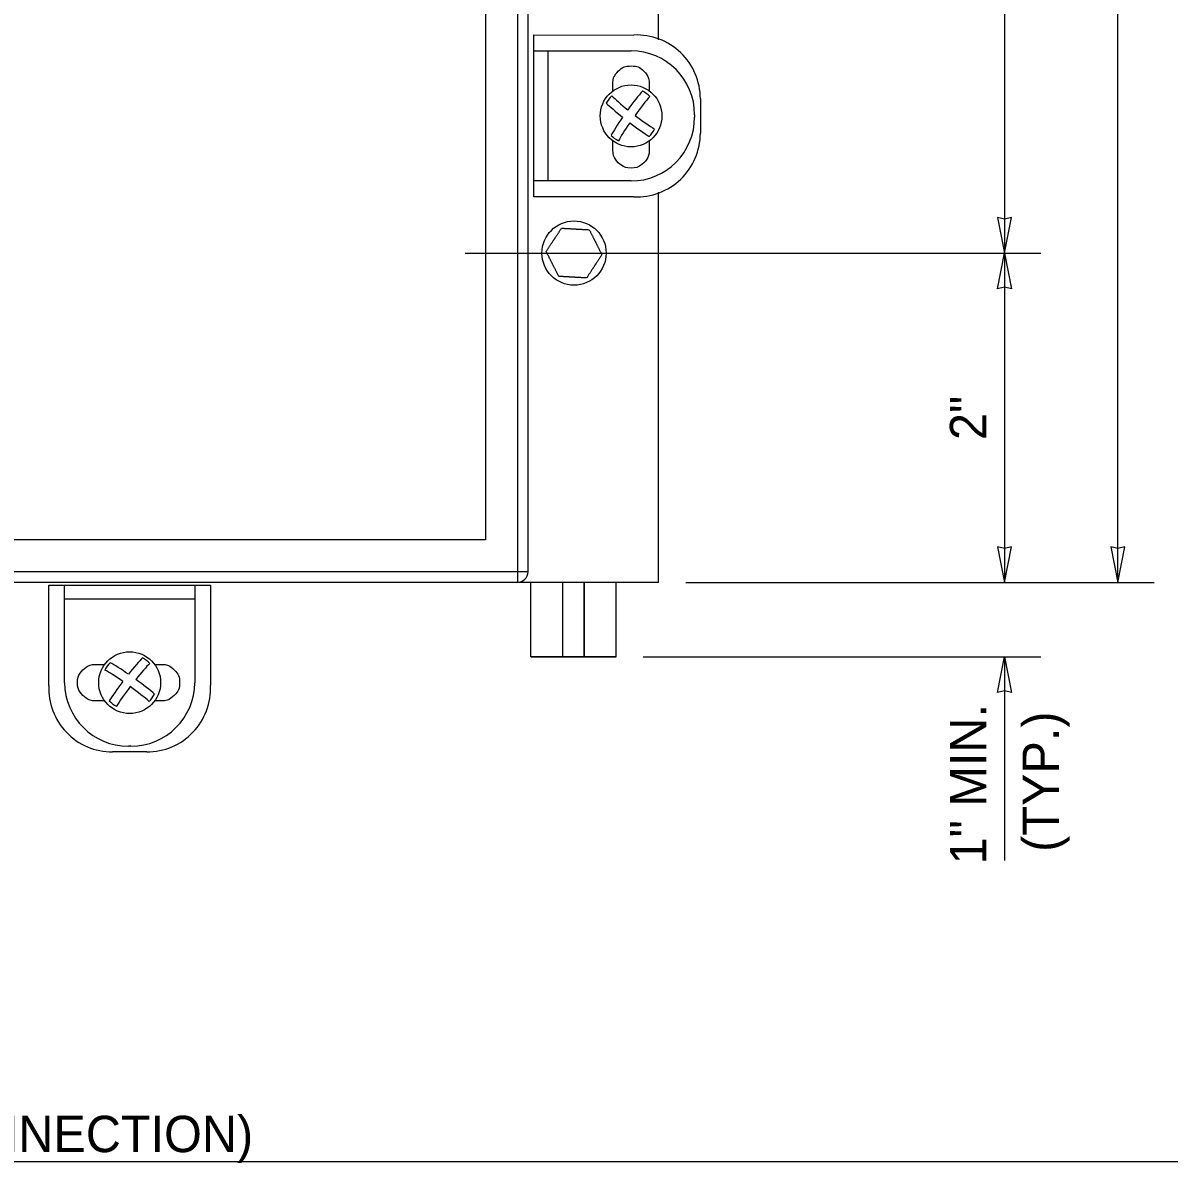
# Model space of a CAD drawing. Extents: x 99862 to 104211, y 98939 to 102076.
# Drawn here: x 101435 to 101940, y 99999 to 100501 of the extents above; entities that cross this region are included whole.
import ezdxf

# ---------------------------------------------------------------- set-up
doc = ezdxf.new("R2010")
doc.units = 0
for name, color, linetype in [('Level 1', 7, 'Continuous'), ('Level 11', 7, 'Continuous'), ('Level 15', 7, 'Continuous'), ('Level 17', 7, 'Continuous'), ('Level 18', 7, 'Continuous'), ('Level 19', 7, 'Continuous'), ('Level 20', 7, 'Continuous'), ('Level 6', 7, 'Continuous'), ('Level 9', 7, 'Continuous')]:
    doc.layers.add(name, color=color, linetype=linetype)

msp = doc.modelspace()

# ---------------------------------------------------------------- linework, layer by layer
at = {"layer": 'Level 1'}
for p, q in [((101652.84, 101082.12), (101652.84, 100254.51)), ((101657.52, 101077.44), (101657.52, 100259.2)), ((101638.77, 101063.37), (101638.77, 100273.26)), ((101638.77, 100273.26), (101021.35, 100273.26)), ((101657.52, 100259.2), (100982.51, 100259.2)), ((101652.84, 100254.51), (100987.19, 100254.51))]:
    msp.add_line(p, q, dxfattribs=at)
msp.add_lwpolyline([(99862, 99999.5), (103151, 99999.5), (103151, 102075.5), (99862, 102075.5)], close=True, dxfattribs=at)
msp.add_arc((101652.84, 100259.2), 4.69, 270, 360, dxfattribs=at)
at = {"layer": 'Level 11'}
for centre, major_axis in [((101702.93, 100459.93), (0, 13.65)), ((101482.08, 100210.36), (13.65, 0))]:
    msp.add_ellipse(centre, major_axis=major_axis, ratio=0.995235, dxfattribs=at)
for centre, major_axis, ratio, start_param, end_param in [((101702.64, 100459.84), (-3.51, 11.61), 0.995235, 0.450926, 0.782886), ((101704.61, 100461.66), (-11.37, 8.76), 0.079461, 0.529016, 1.356129), ((101701.79, 100461.08), (8.35, 11.69), 0.079461, 0.642258, 1.493468), ((101705.04, 100458.76), (-8.35, -11.68), 0.079461, 3.784049, 4.646796), ((101702.63, 100459.93), (0, -12.13), 0.995235, 2.356141, 2.688101), ((101702.17, 100458.5), (11.38, -8.77), 0.079461, 3.67041, 4.509515), ((101701.79, 100461.08), (8.35, 11.69), 0.079461, 1.773671, 2.612775), ((101705.04, 100458.76), (-8.35, -11.68), 0.079461, 4.927057, 5.75417), ((101702.17, 100458.5), (11.38, -8.77), 0.079461, 4.789717, 5.640927), ((101704.61, 100461.66), (-11.37, 8.76), 0.079461, 1.636389, 2.499136), ((101702.64, 100459.84), (-3.51, 11.61), 0.995235, 3.595085, 3.927044), ((101702.63, 100459.93), (0, -12.13), 0.995235, 5.5003, 5.83226), ((101480.65, 100211.11), (-8.77, -11.38), 0.079461, 3.67041, 4.509515), ((101482, 100210.64), (11.61, 3.51), 0.995235, 0.450926, 0.782886), ((101482.08, 100210.65), (-12.13, 0), 0.995235, 5.5003, 5.83226), ((101480.91, 100208.24), (-11.68, 8.35), 0.079461, 4.927057, 5.75417), ((101483.24, 100211.49), (11.69, -8.35), 0.079461, 1.773671, 2.612775), ((101483.82, 100208.67), (8.76, 11.37), 0.079461, 0.529016, 1.356129), ((101480.65, 100211.11), (-8.77, -11.38), 0.079461, 4.789717, 5.640927), ((101483.24, 100211.49), (11.69, -8.35), 0.079461, 0.642258, 1.493468), ((101483.82, 100208.67), (8.76, 11.37), 0.079461, 1.636389, 2.499136), ((101480.91, 100208.24), (-11.68, 8.35), 0.079461, 3.784049, 4.646796), ((101482.08, 100210.65), (-12.13, 0), 0.995235, 2.356141, 2.688101), ((101482, 100210.64), (11.61, 3.51), 0.995235, 3.595085, 3.927044)]:
    msp.add_ellipse(centre, major_axis=major_axis, ratio=ratio, start_param=start_param, end_param=end_param, dxfattribs=at)
at = {"layer": 'Level 15'}
for p, q in [((101917.34, 100254.51), (101917.34, 101082.12)), ((101867.34, 100668.32), (101867.34, 100399.54)), ((101629.8, 100399.54), (101883.34, 100399.54)), ((101867.34, 100399.54), (101867.34, 100254.51)), ((101727.06, 100254.51), (101933.34, 100254.51)), ((101708.31, 100221.7), (101883.34, 100221.7)), ((101867.34, 100221.7), (101867.34, 100132.03))]:
    msp.add_line(p, q, dxfattribs=at)
for points in [[(101867.34, 100399.54), (101870.43, 100415.26), (101867.34, 100414.53), (101864.26, 100415.26)], [(101867.34, 100399.54), (101870.43, 100383.81), (101867.34, 100384.54), (101864.26, 100383.81)], [(101867.34, 100254.51), (101870.43, 100270.24), (101867.34, 100269.51), (101864.26, 100270.24)], [(101917.34, 100254.51), (101920.43, 100270.24), (101917.34, 100269.51), (101914.26, 100270.24)], [(101867.34, 100221.7), (101870.43, 100205.98), (101867.34, 100206.7), (101864.26, 100205.98)]]:
    msp.add_lwpolyline(points, close=True, dxfattribs=at)
at = {"layer": 'Level 17'}
for p, q in [((101658.81, 100221.7), (101658.81, 100254.51)), ((101682.25, 100254.51), (101682.25, 100221.7)), ((101682.25, 100221.7), (101682.25, 100254.51)), ((101658.81, 100221.7), (101658.81, 100221.7)), ((101663.5, 100221.7), (101663.5, 100221.7))]:
    msp.add_line(p, q, dxfattribs=at)
for points in [[(101658.81, 100221.7), (101672.87, 100221.7), (101672.87, 100254.51)], [(101696.31, 100221.7), (101658.81, 100221.7), (101658.81, 100254.51)], [(101672.87, 100221.7), (101672.87, 100254.51)], [(101682.25, 100221.7), (101696.31, 100221.7), (101696.31, 100254.51)], [(101696.31, 100221.7), (101696.31, 100254.51)], [(101663.5, 100221.7), (101691.62, 100221.7), (101691.62, 100221.7)], [(101668.19, 100221.7), (101663.5, 100221.7), (101663.5, 100221.7)], [(101672.87, 100221.7), (101668.19, 100221.7), (101668.19, 100221.7)], [(101668.19, 100221.7), (101668.19, 100221.7), (101668.19, 100221.7)], [(101682.25, 100221.7), (101682.25, 100221.7), (101686.94, 100221.7), (101686.94, 100221.7)], [(101691.62, 100221.7), (101686.94, 100221.7), (101686.94, 100221.7)], [(101691.62, 100221.7), (101691.62, 100221.7), (101691.62, 100221.7)]]:
    msp.add_lwpolyline(points, dxfattribs=at)
at = {"layer": 'Level 18'}
for p, q in [((101696.24, 100254.51), (101652.84, 100254.51)), ((101715.06, 100254.51), (101696.26, 100254.51))]:
    msp.add_line(p, q, dxfattribs=at)
for points in [[(101715.06, 100493.46), (101715.06, 100555.19)], [(101715.06, 100254.51), (101715.06, 100426.4)]]:
    msp.add_lwpolyline(points, dxfattribs=at)
at = {"layer": 'Level 19'}
msp.add_circle((101677.8, 100399.54), 14.14, dxfattribs=at)
for points in [[(101665.53, 100400.23), (101667.76, 100403.63), (101670.03, 100407.1), (101672.26, 100410.5)], [(101672.26, 100410.5), (101676.35, 100410.27), (101680.44, 100410.04), (101684.53, 100409.81)], [(101684.53, 100409.81), (101686.37, 100406.15), (101688.22, 100402.5), (101690.06, 100398.84)], [(101671.06, 100389.26), (101669.22, 100392.92), (101667.38, 100396.57), (101665.53, 100400.23)], [(101690.06, 100398.84), (101687.83, 100395.44), (101685.56, 100391.97), (101683.33, 100388.57)], [(101683.33, 100388.57), (101679.24, 100388.8), (101675.15, 100389.03), (101671.06, 100389.26)]]:
    msp.add_open_spline(points, degree=2, dxfattribs=at)
at = {"layer": 'Level 6'}
for p, q in [((101660.06, 100495.57), (101704.19, 100495.54)), ((101733.44, 100467.45), (101733.44, 100452.41)), ((101704.19, 100424.32), (101660.06, 100424.29)), ((101446.47, 100209.09), (101446.44, 100253.23)), ((101517.72, 100253.23), (101517.7, 100209.09)), ((101489.6, 100179.84), (101474.57, 100179.84))]:
    msp.add_line(p, q, dxfattribs=at)
for centre, major_axis, start_param, end_param in [((101705.45, 100467.45), (0, 28.12), 4.712389, 6.328322), ((101705.45, 100452.41), (0, 28.12), 3.096456, 4.712389), ((101474.57, 100207.83), (28.12, 0), 3.096456, 4.712389), ((101489.6, 100207.83), (28.12, 0), 4.712389, 6.328322)]:
    msp.add_ellipse(centre, major_axis=major_axis, ratio=0.995235, start_param=start_param, end_param=end_param, dxfattribs=at)
at = {"layer": 'Level 9'}
for p, q in [((101660.06, 100424.29), (101660.06, 100495.57)), ((101660.06, 100488.57), (101672.33, 100488.57)), ((101666.19, 100488.57), (101666.19, 100431.29)), ((101672.33, 100488.57), (101674.95, 100488.57)), ((101674.95, 100488.57), (101679.64, 100488.57)), ((101679.65, 100488.57), (101702.93, 100488.57)), ((101694.91, 100470.95), (101694.91, 100473.89)), ((101710.94, 100473.89), (101710.94, 100470.95)), ((101730.92, 100460.45), (101730.92, 100459.41)), ((101694.91, 100445.02), (101694.91, 100448.91)), ((101710.94, 100448.91), (101710.94, 100445.02)), ((101672.33, 100431.29), (101660.06, 100431.29)), ((101674.95, 100431.29), (101672.33, 100431.29)), ((101679.64, 100431.29), (101674.95, 100431.29)), ((101702.93, 100431.29), (101679.65, 100431.29)), ((101446.44, 100253.23), (101517.72, 100253.23)), ((101453.44, 100240.96), (101453.44, 100253.23)), ((101510.72, 100253.23), (101510.72, 100240.96)), ((101510.72, 100247.09), (101453.44, 100247.09)), ((101453.44, 100238.33), (101453.44, 100240.96)), ((101510.72, 100240.96), (101510.72, 100238.33)), ((101453.44, 100233.64), (101453.44, 100238.33)), ((101510.72, 100238.33), (101510.72, 100233.64)), ((101453.44, 100210.36), (101453.44, 100233.64)), ((101510.72, 100233.64), (101510.72, 100210.36)), ((101467.17, 100218.37), (101471.06, 100218.37)), ((101493.11, 100218.37), (101496.05, 100218.37)), ((101471.06, 100202.35), (101467.17, 100202.35)), ((101496.05, 100202.35), (101493.11, 100202.35)), ((101482.6, 100182.37), (101481.57, 100182.37))]:
    msp.add_line(p, q, dxfattribs=at)
for centre, major_axis, start_param, end_param in [((101702.93, 100460.45), (0, 28.12), 4.712389, 6.283185), ((101702.93, 100459.41), (0, 28.12), 3.141593, 4.712389), ((101481.57, 100210.36), (28.12, 0), 3.141593, 4.712389), ((101482.6, 100210.36), (28.12, 0), 4.712389, 6.283185)]:
    msp.add_ellipse(centre, major_axis=major_axis, ratio=0.995235, start_param=start_param, end_param=end_param, dxfattribs=at)
for points in [[(101694.91, 100473.89), (101694.91, 100473.89), (101694.91, 100473.89), (101694.91, 100476.04), (101695.76, 100478.1), (101698.78, 100481.13), (101700.81, 100481.97), (101705.05, 100481.97), (101707.08, 100481.13), (101710.09, 100478.1), (101710.94, 100476.04), (101710.94, 100473.89)], [(101702.93, 100436.94), (101700.81, 100436.94), (101698.78, 100437.78), (101695.76, 100440.81), (101694.91, 100442.87), (101694.91, 100445.02)], [(101710.94, 100445.02), (101710.94, 100442.87), (101710.09, 100440.81), (101707.08, 100437.78), (101705.05, 100436.94), (101702.93, 100436.94)], [(101459.1, 100210.36), (101459.1, 100212.48), (101459.94, 100214.51), (101462.97, 100217.52), (101465.02, 100218.37), (101467.17, 100218.37)], [(101496.05, 100218.37), (101496.05, 100218.37), (101496.05, 100218.37), (101498.2, 100218.37), (101500.25, 100217.52), (101503.28, 100214.51), (101504.12, 100212.48), (101504.12, 100208.24), (101503.28, 100206.21), (101500.25, 100203.19), (101498.2, 100202.35), (101496.05, 100202.35)], [(101467.17, 100202.35), (101465.02, 100202.35), (101462.97, 100203.19), (101459.94, 100206.21), (101459.1, 100208.24), (101459.1, 100210.36)]]:
    msp.add_open_spline(points, degree=3, dxfattribs=at)

# ---------------------------------------------------------------- texts
at = {"layer": 'Level 20'}
for s, p in [('2"', (101859.34, 100317.21)), ('1" MIN.', (101859.34, 100130.34)), ('(TYP.)', (101891.34, 100135.86))]:
    msp.add_text(s, height=16, rotation=90, dxfattribs=at).set_placement(p)
msp.add_text('(DOOR OPEN TO SHOW WIRE CONNECTION)', height=16, dxfattribs=at).set_placement((101071.71, 100003.63))

doc.saveas('drawing.dxf')
